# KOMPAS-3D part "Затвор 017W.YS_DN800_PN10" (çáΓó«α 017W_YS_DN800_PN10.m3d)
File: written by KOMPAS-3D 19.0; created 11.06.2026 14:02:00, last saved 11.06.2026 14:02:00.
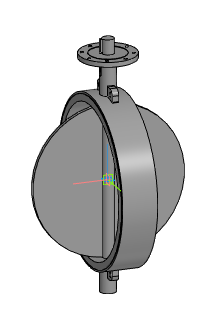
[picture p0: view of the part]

Document properties: Автор: Евгений; Полное имя файла: Z:\3.Личные\kachalov\001_3d для проектировщиков\x.x Тип 017W.Y(S) Затвор дисковый поворотный межфланцевый\_stp_Затвор 017W.YS_DN32-DN1200\Затвор 017W_YS_DN800_PN10.m3d

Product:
- Part/product: Затвор 017W.YS_DN800_PN10

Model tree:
1. Операция без истории:1  (labels: Затвор 017W.YS_DN800_PN10)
